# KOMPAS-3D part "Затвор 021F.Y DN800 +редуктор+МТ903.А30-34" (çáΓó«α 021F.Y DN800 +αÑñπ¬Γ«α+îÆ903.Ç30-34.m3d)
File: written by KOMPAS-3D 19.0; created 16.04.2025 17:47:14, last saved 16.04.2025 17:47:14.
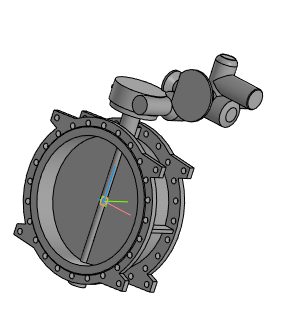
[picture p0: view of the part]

Document properties: Полное имя файла: Затвор 021F.Y DN800 +редуктор+МТ903.А30-34.a3d

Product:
- Part/product: Затвор 021F.Y DN800 +редуктор+МТ903.А30-34
    Масса: 737.482

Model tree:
1. Операция без истории:1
